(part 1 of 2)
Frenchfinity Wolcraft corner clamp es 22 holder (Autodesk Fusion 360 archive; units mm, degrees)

design "Wolcraft corner clamp es 22 holder" references "Base"
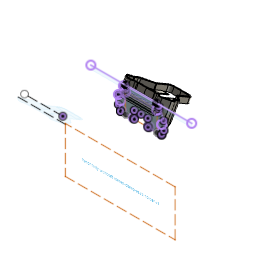
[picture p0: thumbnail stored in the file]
parameter "padding" = 2
parameter "wall_thickness" = 3
component_insert "Component Insert"
canvas "Canvas5"
sketch "Reference" plane through (0, 0, 0) normal (0, 0, 1) x axis (1, 0, 0)
  line L1 (7.1498, 37.8606) -> (8.7854, 10.1726)
  line L2 (26.4622, -5.6256) -> (8.7854, 10.1726)
  line L3 (28.6559, -18.1029) -> (28.1216, -9.0589)
  line L4 (34.1914, -23.0501) -> (28.6559, -18.1029)
  line L5 (25.086, -36.2395) -> (34.3498, -25.8741)
  line L6 (15.5018, -31.9562) -> (22.4922, -36.5753)
  line L7 (11, -31.9562) -> (15.5018, -31.9562)
  line L8 (9.4019, -31.2884) -> (11, -31.9562)
  line L9 (-7.5524, -32.5215) -> (-11.7572, 42.0357)
  line L10 (-7.5524, -32.5215) -> (9.4019, -31.2884)
  line L11 (-11.7572, 42.0357) -> (1.9669, 42.5621)
  line L12 (-7.5524, -32.5215) -> (-24.5378, -33.2026)
  line L13 (-24.5378, -33.2026) -> (-26.0507, -34.0457)
  line L14 (-26.0507, -34.0457) -> (-30.5239, -34.5519)
  line L15 (-30.5239, -34.5519) -> (-36.9506, -39.9278)
  line L16 (-39.5658, -39.8857) -> (-49.9363, -30.6276)
  line L17 (-50.0964, -27.8037) -> (-45.1522, -22.2655)
  line L18 (-45.1522, -22.2655) -> (-45.6382, -13.2187)
  line L19 (-44.3754, -9.6207) -> (-28.587, 8.0649)
  line L20 (-30.075, 35.7612) -> (-28.587, 8.0649)
  line L21 (-11.7572, 42.0357) -> (-25.4535, 41.0157)
  arc A1 centre (2.1585, 37.5658) radius 5 clockwise from (1.9669, 42.5621) to (7.1498, 37.8606)
  arc A2 centre (23.1303, -9.3537) radius 5 clockwise from (26.4622, -5.6256) to (28.1216, -9.0589)
  arc A3 centre (32.8586, -24.5413) radius 2 clockwise from (34.1914, -23.0501) to (34.3498, -25.8741)
  arc A4 centre (23.5948, -34.9067) radius 2 clockwise from (25.086, -36.2395) to (22.4922, -36.5753)
  arc A5 centre (-38.2338, -38.3937) radius 2 clockwise from (-36.9506, -39.9278) to (-39.5658, -39.8857)
  arc A6 centre (-48.6044, -29.1356) radius 2 clockwise from (-49.9363, -30.6276) to (-50.0964, -27.8037)
  arc A7 centre (-40.6455, -12.9505) radius 5 clockwise from (-45.6382, -13.2187) to (-44.3754, -9.6207)
  arc A8 centre (-25.0822, 36.0295) radius 5 clockwise from (-30.075, 35.7612) to (-25.4535, 41.0157)
  point P2 (8.7854, 10.1726)
  point P35 (-28.587, 8.0649)
  point P3 (9.4019, -31.2884)
  point P21 (-24.5378, -33.2026)
  point P4 (28.6559, -18.1029)
  point P31 (-45.1522, -22.2655)
  point P5 (15.5018, -31.9562)
  point P24 (-30.5239, -34.5519)
  point P6 (11, -31.9562)
  point P23 (-26.0507, -34.0457)
  point P7 (-11.7572, 42.0357)
  point P39 (-11.7572, 42.0357)
  point P8 (-7.5524, -32.5215)
  point P22 (-7.5524, -32.5215)
  point P9 (7.1498, 37.8606)
  point P36 (-30.075, 35.7612)
  point P10 (1.9669, 42.5621)
  point P38 (-25.4535, 41.0157)
  point P12 (26.4622, -5.6256)
  point P34 (-44.3754, -9.6207)
  point P13 (28.1216, -9.0589)
  point P32 (-45.6382, -13.2187)
  point P15 (34.1914, -23.0501)
  point P30 (-50.0964, -27.8037)
  point P16 (34.3498, -25.8741)
  point P28 (-49.9363, -30.6276)
  point P18 (25.086, -36.2395)
  point P27 (-39.5658, -39.8857)
  point P19 (22.4922, -36.5753)
  point P25 (-36.9506, -39.9278)
  parallel L2 L4
  perpendicular L4 L5
  horizontal L7
  tangent L1 A1
  tangent L11 A1
  tangent L2 A2
  tangent L3 A2
  equal A1 A2
  tangent L4 A3
  tangent L5 A3
  tangent L5 A4
  tangent L6 A4
  symmetric P2 L9 P35
  symmetric P3 L9 P21
  symmetric P4 L9 P31
  symmetric P5 L9 P24
  symmetric P6 L9 P23
  symmetric P7 L9 P39
  symmetric P8 L9 P22
  symmetric L9 P9 P36
  symmetric L9 P10 P38
  symmetric L9 A1 A8
  symmetric L9 P12 P34
  symmetric L9 P13 P32
  symmetric L9 A2 A7
  symmetric L9 P15 P30
  symmetric L9 P16 P28
  symmetric L9 A3 A6
  symmetric L9 P18 P27
  symmetric L9 P19 P25
  symmetric L9 A4 A5
  dimension "d60" radius A1 = 5
  dimension "d61" radius A3 = 2
  dimension "d62" radius A4 = 2
sketch "Correct size" plane through (0, 0, 0) normal (0, 0, 1) x axis (1, 0, 0)
  line L1 (-7.5524, -32.5215) -> (-24.5378, -33.2026)
  line L2 (-24.5378, -33.2026) -> (-26.0507, -34.0457)
  line L3 (-26.0507, -34.0457) -> (-30.5239, -34.5519)
  line L4 (-30.5239, -34.5519) -> (-36.9506, -39.9278)
  line L5 (-39.5658, -39.8857) -> (-49.9363, -30.6276)
  line L6 (-50.0964, -27.8037) -> (-45.1522, -22.2655)
  line L7 (-45.1522, -22.2655) -> (-45.6382, -13.2187)
  line L8 (-44.3754, -9.6207) -> (-28.587, 8.0649)
  line L9 (-11.7572, 42.0357) -> (-25.4535, 41.0157)
  line L10 (-30.075, 35.7612) -> (-28.587, 8.0649)
  line L11 (-11.7572, 42.0357) -> (1.9669, 42.5621)
  line L12 (-7.5524, -32.5215) -> (9.4019, -31.2884)
  line L13 (9.4019, -31.2884) -> (11, -31.9562)
  line L14 (11, -31.9562) -> (15.5018, -31.9562)
  line L15 (15.5018, -31.9562) -> (22.4922, -36.5753)
  line L16 (25.086, -36.2395) -> (34.3498, -25.8741)
  line L17 (34.1914, -23.0501) -> (28.6559, -18.1029)
  line L18 (28.6559, -18.1029) -> (28.1216, -9.0589)
  line L19 (26.4622, -5.6256) -> (8.7854, 10.1726)
  line L20 (7.1498, 37.8606) -> (8.7854, 10.1726)
  line L21 (-11.7009, 41.0371) -> (2.0052, 41.5629)
  line L22 (-11.7009, 41.0371) -> (-25.3792, 40.0184)
  line L23 (-29.0764, 35.8149) -> (-27.5663, 7.7066)
  line L24 (-43.6294, -10.2867) -> (-27.5663, 7.7066)
  line L25 (-44.1315, -22.6237) -> (-44.6397, -13.1651)
  line L26 (-49.3504, -28.4697) -> (-44.1315, -22.6237)
  line L27 (-38.8998, -39.1397) -> (-49.2703, -29.8816)
  line L28 (-30.935, -33.592) -> (-37.5922, -39.1607)
  line L29 (-26.3624, -33.0746) -> (-30.935, -33.592)
  line L30 (-24.8163, -32.2129) -> (-26.3624, -33.0746)
  line L31 (-7.6087, -31.5229) -> (-24.8163, -32.2129)
  line L32 (-7.6087, -31.5229) -> (9.5674, -30.2738)
  line L33 (9.5674, -30.2738) -> (11.2005, -30.9562)
  line L34 (11.2005, -30.9562) -> (15.8023, -30.9562)
  line L35 (15.8023, -30.9562) -> (23.0435, -35.741)
  line L36 (24.3404, -35.5731) -> (33.6042, -25.2077)
  line L37 (33.525, -23.7957) -> (27.6819, -18.5736)
  line L38 (27.6819, -18.5736) -> (27.1234, -9.1178)
  line L39 (25.7958, -6.3712) -> (7.8115, 9.7019)
  line L40 (6.1516, 37.8017) -> (7.8115, 9.7019)
  line L41 (-11.7009, 41.0371) -> (-7.6087, -31.5229)
  line L42 (7.8115, 9.7019) -> (-27.5663, 7.7066)
  arc A1 centre (-38.2338, -38.3937) radius 2 clockwise from (-36.9506, -39.9278) to (-39.5658, -39.8857)
  arc A2 centre (-48.6044, -29.1356) radius 2 clockwise from (-49.9363, -30.6276) to (-50.0964, -27.8037)
  arc A3 centre (-40.6455, -12.9505) radius 5 clockwise from (-45.6382, -13.2187) to (-44.3754, -9.6207)
  arc A4 centre (-25.0822, 36.0295) radius 5 clockwise from (-30.075, 35.7612) to (-25.4535, 41.0157)
  arc A5 centre (23.5948, -34.9067) radius 2 clockwise from (25.086, -36.2395) to (22.4922, -36.5753)
  arc A6 centre (32.8586, -24.5413) radius 2 clockwise from (34.1914, -23.0501) to (34.3498, -25.8741)
  arc A7 centre (23.1303, -9.3537) radius 5 clockwise from (26.4622, -5.6256) to (28.1216, -9.0589)
  arc A8 centre (2.1585, 37.5658) radius 5 clockwise from (1.9669, 42.5621) to (7.1498, 37.8606)
  arc A9 centre (-25.0822, 36.0295) radius 4 clockwise from (-29.0764, 35.8149) to (-25.3792, 40.0184)
  arc A10 centre (-40.6455, -12.9505) radius 4 clockwise from (-44.6397, -13.1651) to (-43.6294, -10.2867)
  arc A11 centre (-48.6044, -29.1356) radius 1 clockwise from (-49.2703, -29.8816) to (-49.3504, -28.4697)
  arc A12 centre (-38.2338, -38.3937) radius 1 clockwise from (-37.5922, -39.1607) to (-38.8998, -39.1397)
  arc A13 centre (23.5948, -34.9067) radius 1 clockwise from (24.3404, -35.5731) to (23.0435, -35.741)
  arc A14 centre (32.8586, -24.5413) radius 1 clockwise from (33.525, -23.7957) to (33.6042, -25.2077)
  arc A15 centre (23.1303, -9.3537) radius 4 clockwise from (25.7958, -6.3712) to (27.1234, -9.1178)
  arc A16 centre (2.1585, 37.5658) radius 4 clockwise from (2.0052, 41.5629) to (6.1516, 37.8017)
  point P41 (-11.7009, 41.0371)
  point P59 (-7.6087, -31.5229)
  point P45 (-27.5663, 7.7066)
  point P73 (7.8115, 9.7019)
  dimension "d64" = -1
  dimension "d65" distance P41 P59 = 72.56
  dimension "d66" distance P45 P73 = 35.3778
sketch "Base" plane through (0, 0, 0) normal (0, 0, 1) x axis (1, 0, 0)
  line L1 (-11.7009, 41.0371) -> (-25.3792, 40.0184)
  line L2 (-11.7009, 41.0371) -> (2.0052, 41.5629)
  line L3 (6.1516, 37.8017) -> (7.8115, 9.7019)
  line L4 (25.7958, -6.3712) -> (7.8115, 9.7019)
  line L5 (27.6819, -18.5736) -> (27.1234, -9.1178)
  line L6 (33.525, -23.7957) -> (27.6819, -18.5736)
  line L7 (24.3404, -35.5731) -> (33.6042, -25.2077)
  line L8 (15.8023, -30.9562) -> (23.0435, -35.741)
  line L9 (11.2005, -30.9562) -> (15.8023, -30.9562)
  line L10 (9.5674, -30.2738) -> (11.2005, -30.9562)
  line L11 (-7.6087, -31.5229) -> (9.5674, -30.2738)
  line L12 (-7.6087, -31.5229) -> (-24.8163, -32.2129)
  line L13 (-24.8163, -32.2129) -> (-26.3624, -33.0746)
  line L14 (-26.3624, -33.0746) -> (-30.935, -33.592)
  line L15 (-30.935, -33.592) -> (-37.5922, -39.1607)
  line L16 (-38.8998, -39.1397) -> (-49.2703, -29.8816)
  line L17 (-49.3504, -28.4697) -> (-44.1315, -22.6237)
  line L18 (-44.1315, -22.6237) -> (-44.6397, -13.1651)
  line L19 (-43.6294, -10.2867) -> (-27.5663, 7.7066)
  line L20 (-29.0764, 35.8149) -> (-27.5663, 7.7066)
  line L21 (-11.8135, 43.0342) -> (1.9286, 43.5614)
  line L22 (-11.8135, 43.0342) -> (-25.5278, 42.0129)
  line L23 (-31.0735, 35.7076) -> (-29.6077, 8.4231)
  line L24 (-45.1214, -8.9547) -> (-29.6077, 8.4231)
  line L25 (-46.1729, -21.9072) -> (-46.6368, -13.2724)
  line L26 (-50.8423, -27.1378) -> (-46.1729, -21.9072)
  line L27 (-40.2317, -40.6316) -> (-50.6023, -31.3736)
  line L28 (-30.1128, -35.5118) -> (-36.309, -40.6948)
  line L29 (-25.739, -35.0169) -> (-30.1128, -35.5118)
  line L30 (-24.2594, -34.1922) -> (-25.739, -35.0169)
  line L31 (-7.4961, -33.52) -> (-24.2594, -34.1922)
  line L32 (-7.4961, -33.52) -> (9.2365, -32.3031)
  line L33 (9.2365, -32.3031) -> (10.7995, -32.9562)
  line L34 (10.7995, -32.9562) -> (15.2012, -32.9562)
  line L35 (15.2012, -32.9562) -> (21.9409, -37.4096)
  line L36 (25.8316, -36.9058) -> (35.0955, -26.5404)
  line L37 (34.8577, -22.3045) -> (29.6298, -17.6321)
  line L38 (29.6298, -17.6321) -> (29.1199, -8.9999)
  line L39 (27.1286, -4.88) -> (9.7594, 10.6433)
  line L40 (8.1481, 37.9196) -> (9.7594, 10.6433)
  line L41 (-11.9825, 46.03) -> (1.8136, 46.5592)
  line L42 (-11.9825, 46.03) -> (-25.7506, 45.0046)
  line L43 (-34.0692, 35.5467) -> (-32.6698, 9.4979)
  line L44 (-47.3593, -6.9569) -> (-32.6698, 9.4979)
  line L45 (-49.235, -20.8325) -> (-49.6325, -13.4333)
  line L46 (-53.0803, -25.1399) -> (-49.235, -20.8325)
  line L47 (-42.2296, -42.8696) -> (-52.6002, -33.6116)
  line L48 (-28.8796, -38.3914) -> (-34.3842, -42.9959)
  line L49 (-24.8039, -37.9302) -> (-28.8796, -38.3914)
  line L50 (-23.424, -37.1611) -> (-24.8039, -37.9302)
  line L51 (-7.3271, -36.5157) -> (-23.424, -37.1611)
  line L52 (-7.3271, -36.5157) -> (8.7403, -35.3471)
  line L53 (8.7403, -35.3471) -> (10.1979, -35.9562)
  line L54 (10.1979, -35.9562) -> (14.2996, -35.9562)
  line L55 (14.2996, -35.9562) -> (20.287, -39.9126)
  line L56 (28.0685, -38.905) -> (37.3323, -28.5396)
  line L57 (36.8569, -20.0676) -> (32.5516, -16.2199)
  line L58 (32.5516, -16.2199) -> (32.1147, -8.823)
  line L59 (29.1277, -2.6432) -> (12.6812, 12.0556)
  line L60 (11.1429, 38.0965) -> (12.6812, 12.0556)
  line L61 (-7.4961, -33.52) -> (-7.6087, -31.5229)
  line L62 (-7.9465, -25.5327) -> (-7.4961, -33.52)
  line L63 (-21.4357, -26.0736) -> (-7.9465, -25.5327)
  line L64 (-21.9988, -16.0895) -> (-21.4357, -26.0736)
  line L65 (-11.7009, 41.0371) -> (-7.6087, -31.5229)
  line L66 (-8.5096, -15.5486) -> (-21.9988, -16.0895)
  line L67 (-15.504, -15.829) -> (-8.5096, -15.5486)
  line L68 (-18.7944, 42.5144) -> (-15.504, -15.829)
  line L69 (-7.5524, -32.5215) -> (-11.7572, 42.0357)
  line L70 (-11.8135, 43.0342) -> (-11.7009, 41.0371)
  line L71 (-11.0252, 29.0564) -> (-11.8135, 43.0342)
  line L72 (-30.6595, 28.0016) -> (-11.0252, 29.0564)
  line L73 (8.6032, 30.2159) -> (-11.0252, 29.0564)
  line L74 (-4.8185, 43.3026) -> (-1.5281, -15.0408)
  line L75 (-8.5096, -15.5486) -> (4.9548, -14.5693)
  line L76 (4.9548, -14.5693) -> (5.5179, -24.5535)
  line L77 (5.5179, -24.5535) -> (-7.9465, -25.5327)
  arc A1 centre (-25.0822, 36.0295) radius 4 clockwise from (-29.0764, 35.8149) to (-25.3792, 40.0184)
  arc A2 centre (2.1585, 37.5658) radius 4 clockwise from (2.0052, 41.5629) to (6.1516, 37.8017)
  arc A3 centre (23.1303, -9.3537) radius 4 clockwise from (25.7958, -6.3712) to (27.1234, -9.1178)
  arc A4 centre (32.8586, -24.5413) radius 1 clockwise from (33.525, -23.7957) to (33.6042, -25.2077)
  arc A5 centre (23.5948, -34.9067) radius 1 clockwise from (24.3404, -35.5731) to (23.0435, -35.741)
  arc A6 centre (-38.2338, -38.3937) radius 1 clockwise from (-37.5922, -39.1607) to (-38.8998, -39.1397)
  arc A7 centre (-48.6044, -29.1356) radius 1 clockwise from (-49.2703, -29.8816) to (-49.3504, -28.4697)
  arc A8 centre (-40.6455, -12.9505) radius 4 clockwise from (-44.6397, -13.1651) to (-43.6294, -10.2867)
  arc A9 centre (-25.0822, 36.0295) radius 6 clockwise from (-31.0735, 35.7076) to (-25.5278, 42.0129)
  arc A10 centre (-40.6455, -12.9505) radius 6 clockwise from (-46.6368, -13.2724) to (-45.1214, -8.9547)
  arc A11 centre (-48.6044, -29.1356) radius 3 clockwise from (-50.6023, -31.3736) to (-50.8423, -27.1378)
  arc A12 centre (-38.2338, -38.3937) radius 3 clockwise from (-36.309, -40.6948) to (-40.2317, -40.6316)
  arc A13 centre (23.5948, -34.9067) radius 3 clockwise from (25.8316, -36.9058) to (21.9409, -37.4096)
  arc A14 centre (32.8586, -24.5413) radius 3 clockwise from (34.8577, -22.3045) to (35.0955, -26.5404)
  arc A15 centre (23.1303, -9.3537) radius 6 clockwise from (27.1286, -4.88) to (29.1199, -8.9999)
  arc A16 centre (2.1585, 37.5658) radius 6 clockwise from (1.9286, 43.5614) to (8.1481, 37.9196)
  arc A17 centre (-25.0822, 36.0295) radius 9 clockwise from (-34.0692, 35.5467) to (-25.7506, 45.0046)
  arc A18 centre (-40.6455, -12.9505) radius 9 clockwise from (-49.6325, -13.4333) to (-47.3593, -6.9569)
  arc A19 centre (-48.6044, -29.1356) radius 6 clockwise from (-52.6002, -33.6116) to (-53.0803, -25.1399)
  arc A20 centre (-38.2338, -38.3937) radius 6 clockwise from (-34.3842, -42.9959) to (-42.2296, -42.8696)
  arc A21 centre (23.5948, -34.9067) radius 6 clockwise from (28.0685, -38.905) to (20.287, -39.9126)
  arc A22 centre (32.8586, -24.5413) radius 6 clockwise from (36.8569, -20.0676) to (37.3323, -28.5396)
  arc A23 centre (23.1303, -9.3537) radius 9 clockwise from (29.1277, -2.6432) to (32.1147, -8.823)
  arc A24 centre (2.1585, 37.5658) radius 9 clockwise from (1.8136, 46.5592) to (11.1429, 38.0965)
  point P23 (-7.6087, -31.5229)
  point P110 (-7.6087, -31.5229)
  point P116 (-18.7944, 42.5144)
  point P5 (-11.7009, 41.0371)
  point P119 (-11.7009, 41.0371)
  point P121 (-30.6595, 28.0016)
  point P111 (-7.9465, -25.5327)
  point P129 (-7.9465, -25.5327)
  point P112 (-21.4357, -26.0736)
  point P128 (5.5179, -24.5535)
  point P113 (-21.9988, -16.0895)
  point P126 (4.9548, -14.5693)
  point P114 (-8.5096, -15.5486)
  point P127 (-8.5096, -15.5486)
  point P115 (-15.504, -15.829)
  point P124 (-1.5281, -15.0408)
  point P125 (-4.8185, 43.3026)
  point P120 (-11.0252, 29.0564)
  point P122 (-11.0252, 29.0564)
  point P123 (8.6032, 30.2159)
  point P57 (-7.4961, -33.52)
  point P39 (-11.8135, 43.0342)
  coincident P23 P110
  parallel L61 L62
  parallel L12 L63
  parallel L64 L65
  parallel L63 L66
  parallel L66 L67
  coincident L22 P116
  parallel L68 L69
  coincident P5 P119
  parallel L65 L71
  coincident L23 P121
  perpendicular L23 L72
  symmetric P111 L65 P129
  symmetric P112 L65 P128
  symmetric P113 L65 P126
  symmetric L65 P114 P127
  symmetric L65 P115 P124
  symmetric L65 P116 P125
  symmetric L65 P120 P122
  symmetric L65 P121 P123
  dimension "d67" = -2 (= "padding * -1")
  dimension "d68" = -5 (= "( padding + wall_thickness ) * -1")
  dimension "d74" distance P57 P111 = 8
  dimension "d75" distance P111 P112 = 13.5
  dimension "d76" distance P112 P113 = 10
  dimension "d77" distance P113 P114 = 13.5
  dimension "d78" distance P114 P115 = 7
  dimension "d79" distance P39 P120 = 14
extrude "Extrude8" new body sketch "Base" profile of A16 L40 L39 A15 L34 A14 L33 L31 L32 L30 L29 L28 L24 L35 L26 A9 L27 A10 L36 A12 L37 L23 L21 A11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 along normal blind 10
sketch "Sketch16" plane through (0, 0, 0) normal (0, 0, 1) x axis (1, 0, 0)
  line L1 (-11.9825, 46.03) -> (-25.7506, 45.0046)
  line L2 (-11.9825, 46.03) -> (1.8136, 46.5592)
  line L3 (11.1429, 38.0965) -> (12.6812, 12.0556)
  line L4 (29.1277, -2.6432) -> (12.6812, 12.0556)
  line L5 (32.5516, -16.2199) -> (32.1147, -8.823)
  line L6 (36.8569, -20.0676) -> (32.5516, -16.2199)
  line L7 (28.0685, -38.905) -> (37.3323, -28.5396)
  line L8 (14.2996, -35.9562) -> (20.287, -39.9126)
  line L9 (10.1979, -35.9562) -> (14.2996, -35.9562)
  line L10 (8.7403, -35.3471) -> (10.1979, -35.9562)
  line L11 (-7.3271, -36.5157) -> (8.7403, -35.3471)
  line L12 (-7.3271, -36.5157) -> (-23.424, -37.1611)
  line L13 (-23.424, -37.1611) -> (-24.8039, -37.9302)
  line L14 (-24.8039, -37.9302) -> (-28.8796, -38.3914)
  line L15 (-28.8796, -38.3914) -> (-34.3842, -42.9959)
  line L16 (-42.2296, -42.8696) -> (-52.6002, -33.6116)
  line L17 (-53.0803, -25.1399) -> (-49.235, -20.8325)
  line L18 (-49.235, -20.8325) -> (-49.6325, -13.4333)
  line L19 (-47.3593, -6.9569) -> (-32.6698, 9.4979)
  line L20 (-34.0692, 35.5467) -> (-32.6698, 9.4979)
  line L21 (-7.4961, -33.52) -> (-24.2594, -34.1922)
  line L22 (-24.2594, -34.1922) -> (-25.739, -35.0169)
  line L23 (-25.739, -35.0169) -> (-30.1128, -35.5118)
  line L24 (-30.1128, -35.5118) -> (-36.309, -40.6948)
  line L25 (-40.2317, -40.6316) -> (-50.6023, -31.3736)
  line L26 (-50.8423, -27.1378) -> (-46.1729, -21.9072)
  line L27 (-46.1729, -21.9072) -> (-46.6368, -13.2724)
  line L28 (-45.1214, -8.9547) -> (-29.6077, 8.4231)
  line L29 (-11.8135, 43.0342) -> (-25.5278, 42.0129)
  line L30 (-11.8135, 43.0342) -> (1.9286, 43.5614)
  line L31 (8.1481, 37.9196) -> (9.7594, 10.6433)
  line L32 (27.1286, -4.88) -> (9.7594, 10.6433)
  line L33 (29.6298, -17.6321) -> (29.1199, -8.9999)
  line L34 (34.8577, -22.3045) -> (29.6298, -17.6321)
  line L35 (25.8316, -36.9058) -> (35.0955, -26.5404)
  line L36 (15.2012, -32.9562) -> (21.9409, -37.4096)
  line L37 (10.7995, -32.9562) -> (15.2012, -32.9562)
  line L38 (9.2365, -32.3031) -> (10.7995, -32.9562)
  line L39 (-7.4961, -33.52) -> (9.2365, -32.3031)
  line L40 (-31.0735, 35.7076) -> (-29.6077, 8.4231)
  line L41 (-18.7944, 42.5144) -> (-15.504, -15.829)
  line L42 (-4.8185, 43.3026) -> (-1.5281, -15.0408)
  line L43 (-8.5096, -15.5486) -> (-21.9988, -16.0895)
  line L44 (-21.9988, -16.0895) -> (-21.4357, -26.0736)
  line L45 (-21.4357, -26.0736) -> (-7.9465, -25.5327)
  line L46 (5.5179, -24.5535) -> (-7.9465, -25.5327)
  line L47 (4.9548, -14.5693) -> (5.5179, -24.5535)
  line L48 (-8.5096, -15.5486) -> (4.9548, -14.5693)
  line L49 (8.6032, 30.2159) -> (-11.0252, 29.0564)
  line L50 (-30.6595, 28.0016) -> (-11.0252, 29.0564)
  arc A1 centre (-25.0822, 36.0295) radius 9 clockwise from (-34.0692, 35.5467) to (-25.7506, 45.0046)
  arc A2 centre (2.1585, 37.5658) radius 9 clockwise from (1.8136, 46.5592) to (11.1429, 38.0965)
  arc A3 centre (23.1303, -9.3537) radius 9 clockwise from (29.1277, -2.6432) to (32.1147, -8.823)
  arc A4 centre (32.8586, -24.5413) radius 6 clockwise from (36.8569, -20.0676) to (37.3323, -28.5396)
  arc A5 centre (23.5948, -34.9067) radius 6 clockwise from (28.0685, -38.905) to (20.287, -39.9126)
  arc A6 centre (-38.2338, -38.3937) radius 6 clockwise from (-34.3842, -42.9959) to (-42.2296, -42.8696)
  arc A7 centre (-48.6044, -29.1356) radius 6 clockwise from (-52.6002, -33.6116) to (-53.0803, -25.1399)
  arc A8 centre (-40.6455, -12.9505) radius 9 clockwise from (-49.6325, -13.4333) to (-47.3593, -6.9569)
  arc A9 centre (-38.2338, -38.3937) radius 3 clockwise from (-36.309, -40.6948) to (-40.2317, -40.6316)
  arc A10 centre (-48.6044, -29.1356) radius 3 clockwise from (-50.6023, -31.3736) to (-50.8423, -27.1378)
  arc A11 centre (-40.6455, -12.9505) radius 6 clockwise from (-46.6368, -13.2724) to (-45.1214, -8.9547)
  arc A12 centre (-25.0822, 36.0295) radius 6 clockwise from (-31.0735, 35.7076) to (-25.5278, 42.0129)
  arc A13 centre (2.1585, 37.5658) radius 6 clockwise from (1.9286, 43.5614) to (8.1481, 37.9196)
  arc A14 centre (23.1303, -9.3537) radius 6 clockwise from (27.1286, -4.88) to (29.1199, -8.9999)
  arc A15 centre (32.8586, -24.5413) radius 3 clockwise from (34.8577, -22.3045) to (35.0955, -26.5404)
  arc A16 centre (23.5948, -34.9067) radius 3 clockwise from (25.8316, -36.9058) to (21.9409, -37.4096)
extrude "Extrude9" add sketch "Sketch16" against normal blind 1
move "Move1"
sketch "Sketch17" plane through (0, 0, 0) normal (0, 0, 1) x axis (1, 0, 0)
  line L1 (-76, 0) -> (0, 0)
  point P1 (0, 0)
  point P2 (0, 0)
  coincident P1 P2
  horizontal L1
move "Move2"
move "Move3"
move "Move4"
move "Move5"
move "Move6"
sketch "Sketch18" plane through (0, 0, 0) normal (1, 0, 0) x axis (0, 1, 0)
  line L1 (-2.1019, -8.6882) -> (-2.2977, -8.5751)
  line L2 (6.5584, -13.6882) -> (-2.1019, -8.6882)
  line L3 (6.4641, -13.6337) -> (6.5584, -13.6882)
  line L4 (45.0721, -35.9241) -> (6.4641, -13.6337)
  line L5 (45.1067, -35.9441) -> (45.0721, -35.9241)
  line L6 (51.7899, -39.8026) -> (45.1067, -35.9441)
  line L7 (51.7899, -39.8026) -> (56.9689, -42.7927)
  line L8 (57.1774, -42.9131) -> (56.9689, -42.7927)
  line L9 (56.9572, -42.786) -> (57.1774, -42.9131)
  line L10 (51.7733, -39.793) -> (56.9572, -42.786)
  line L11 (45.0901, -35.9345) -> (51.7733, -39.793)
  line L12 (45.0662, -35.9207) -> (45.0901, -35.9345)
  line L13 (6.4582, -13.6303) -> (45.0662, -35.9207)
  line L14 (6.547, -13.6816) -> (6.4582, -13.6303)
  line L15 (-2.1133, -8.6816) -> (6.547, -13.6816)
  line L16 (-2.2977, -8.5751) -> (-2.1133, -8.6816)
  line L17 (15.6697, -18.9486) -> (10.1796, -15.7789)
  line L18 (29.1876, -26.7531) -> (15.6697, -18.9486)
  line L19 (51.779, -39.7963) -> (29.1876, -26.7531)
  line L20 (59.5549, -44.2857) -> (51.779, -39.7963)
  line L21 (59.7759, -44.4133) -> (59.5549, -44.2857)
  line L22 (59.5665, -44.2924) -> (59.7759, -44.4133)
  line L23 (59.5665, -44.2924) -> (51.7981, -39.8073)
  line L24 (29.2067, -26.7642) -> (51.7981, -39.8073)
  line L25 (15.702, -18.9673) -> (29.2067, -26.7642)
  line L26 (15.702, -18.9673) -> (10.2141, -15.7988)
  line L27 (3.7971, -12.0939) -> (10.2141, -15.7988)
  line L28 (0.2619, -10.0529) -> (3.7971, -12.0939)
  line L29 (0.2619, -10.0529) -> (-7.0866, -5.8103)
  line L30 (-15.6014, -0.8942) -> (-7.0866, -5.8103)
  line L31 (-15.6014, -0.8942) -> (-17.1241, -0.0151)
  line L32 (-12.386, -2.7506) -> (-16.0965, -0.6084)
  line L33 (-12.1878, -2.8651) -> (-12.386, -2.7506)
  line L34 (-11.5907, -3.2098) -> (-12.1878, -2.8651)
  line L35 (-11.8243, -3.0749) -> (-11.5907, -3.2098)
  line L36 (-11.6043, -3.202) -> (-11.8243, -3.0749)
  line L37 (-12.2026, -2.8565) -> (-11.6043, -3.202)
  line L38 (-12.4043, -2.7401) -> (-12.2026, -2.8565)
  line L39 (-16.1196, -0.595) -> (-12.4043, -2.7401)
  line L40 (-15.6311, -0.8771) -> (-17.1502, 0)
  line L41 (-7.1246, -5.7883) -> (-15.6311, -0.8771)
  line L42 (0.2239, -10.031) -> (-7.1246, -5.7883)
  line L43 (3.7625, -12.074) -> (0.2239, -10.031)
  line L44 (10.1796, -15.7789) -> (3.7625, -12.074)
  line L45 (-17.1241, -50.0151) -> (-17.1241, -0.0151)
  line L46 (29.2067, -26.7642) -> (34.7067, -17.2379)
  line L47 (-17.1241, -50.0151) -> (29.2067, -26.7642)
  point P33 (-17.1241, -0.0151)
  point P48 (-17.1241, -0.0151)
  point P51 (29.2067, -26.7642)
  point P52 (29.2067, -26.7642)
  point P49 (-17.1241, -50.0151)
  vertical L45
  coincident P33 P48
  coincident P51 P52
  dimension "d82" distance P48 P49 = 50
sketch "Sketch19" plane through (0, -4.2876, -7.4263) normal (0, -0.5, -0.866) x axis (1, 0, 0)
  line L1 (-24.5019, -2.5238) -> (-38, -2.2977)
  line L2 (-24.5068, -12.5238) -> (-24.5019, -2.5238)
  line L3 (-31.0059, -12.4149) -> (-24.5068, -12.5238)
  line L4 (-31.0276, -56.9957) -> (-31.0059, -12.4149)
  line L5 (-18.3641, -57.0356) -> (-31.0276, -56.9957)
  line L6 (-18.3885, -64.7527) -> (-18.3641, -57.0356)
  line L7 (-38.0335, -70.9736) -> (-24.2834, -70.7328)
  line L8 (-51.7833, -70.7194) -> (-38.0335, -70.9736)
  line L9 (-57.6892, -57.0164) -> (-57.6724, -64.7335)
  line L10 (-45.0257, -56.9888) -> (-57.6892, -57.0164)
  line L11 (-45.004, -12.4081) -> (-45.0257, -56.9888)
  line L12 (-51.5032, -12.5106) -> (-45.004, -12.4081)
  line L13 (-51.4983, -2.5106) -> (-51.5032, -12.5106)
  line L14 (-38, -2.2977) -> (-51.4983, -2.5106)
  line L15 (-60.7292, -38.6538) -> (-76.3144, -23.0447)
  line L16 (-60.6724, -64.74) -> (-60.7292, -38.6538)
  line L17 (-38.0349, -73.9741) -> (-51.8388, -73.7189)
  line L18 (-24.2309, -73.7324) -> (-38.0349, -73.9741)
  line L19 (-15.3062, -38.6759) -> (-15.3885, -64.7621)
  line L20 (0.2942, -23.082) -> (-15.3062, -38.6759)
  line L21 (2.9548, -9.3353) -> (2.9315, -16.7451)
  line L22 (7.0386, -5.2533) -> (2.9548, -9.3353)
  line L23 (-2.7876, 13.0641) -> (7.0404, 3.232)
  line L24 (-16.3704, 9.3513) -> (-10.6132, 13.6358)
  line L25 (-20.4657, 9.1224) -> (-16.3704, 9.3513)
  line L26 (-21.887, 8.4329) -> (-20.4657, 9.1224)
  line L27 (-37.9946, 8.7027) -> (-21.887, 8.4329)
  line L28 (-54.1025, 8.4486) -> (-37.9946, 8.7027)
  line L29 (-55.5232, 9.1394) -> (-54.1025, 8.4486)
  line L30 (-59.6182, 9.3724) -> (-55.5232, 9.1394)
  line L31 (-65.3713, 13.6624) -> (-59.6182, 9.3724)
  line L32 (-83.035, 3.2759) -> (-73.1974, 13.0984)
  line L33 (-78.9617, -9.2954) -> (-83.0415, -5.2094)
  line L34 (-78.9456, -16.7052) -> (-78.9617, -9.2954)
  line L35 (8.7969, -1.011) -> (-84.7956, -0.9654)
  arc A1 centre (-24.3884, -64.7337) radius 6 clockwise from (-18.3885, -64.7527) to (-24.2834, -70.7328)
  arc A2 centre (-51.6724, -64.7204) radius 6 clockwise from (-51.7833, -70.7194) to (-57.6724, -64.7335)
  arc A3 centre (-69.9456, -16.6856) radius 9 clockwise from (-76.3144, -23.0447) to (-78.9456, -16.7052)
  arc A4 centre (-51.6724, -64.7204) radius 9 clockwise from (-51.8388, -73.7189) to (-60.6724, -64.74)
  arc A5 centre (-24.3884, -64.7337) radius 9 clockwise from (-15.3885, -64.7621) to (-24.2309, -73.7324)
  arc A6 centre (-6.0685, -16.7167) radius 9 clockwise from (2.9315, -16.7451) to (0.2942, -23.082)
  arc A7 centre (2.7969, -1.0097) radius 6 clockwise from (7.0404, 3.232) to (7.0386, -5.2533)
  arc A8 centre (-7.0311, 8.8224) radius 6 clockwise from (-10.6132, 13.6358) to (-2.7876, 13.0641)
  arc A9 centre (-68.958, 8.8525) radius 6 clockwise from (-73.1974, 13.0984) to (-65.3713, 13.6624)
  arc A10 centre (-78.7956, -0.97) radius 6 clockwise from (-83.0415, -5.2094) to (-83.035, 3.2759)
  point P54 (-84.7956, -0.9654)
  point P55 (8.7969, -1.011)
  midpoint A10 P54
  midpoint A7 P55
extrude "Extrude10" add sketch "Sketch18" profile of L1 L2 L3 L4 L13 L14 L15 L16 L17 L18 L19 L25 L26 L27 L28 L29 L30 L31 L32 L33 L34 L35 L36 L37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 to an object
extrude "Extrude11" add of existing geometry to an object
extrude "Extrude13" cut of existing geometry blind -65
extrude "Extrude14" cut of existing geometry blind -62
extrude "Extrude15" cut sketch "Sketch19" profile of L1 L2 L3 L4 L5 L6 A1 L7 L8 A2 L9 L10 L11 L12 L13 L14 along normal blind 62
extrude "Extrude16" new body of existing geometry blind 50
sketch "Sketch20" plane through (0, 55.6118, 0) normal (0, 1, 0) x axis (-1, 0, 0)
  line L1 (0, 52.6059) -> (-200, 52.6059)
  line L2 (0, 60) -> (0, 52.6059)
  line L3 (-200, 60) -> (0, 60)
  line L4 (-200, 52.6059) -> (-200, 60)
  line L5 (-200, 60) -> (0, 60)
move "Move7"
sketch "Sketch21" plane through (0, 55.6118, 0) normal (0, -1, 0) x axis (1, 0, 0)
  line L1 (113.1884, 10) -> (113.1921, 25.3077)
  line L2 (140.6462, 10) -> (113.1884, 10)
  line L3 (140.6489, 11.6846) -> (140.6462, 10)
  line L4 (144.7326, 19.8488) -> (140.6489, 11.6846)
  line L5 (134.9064, 56.4835) -> (144.7344, 36.8193)
  line L6 (69.3371, 60) -> (130.6629, 60)
  line L7 (68.1349, 60) -> (69.3371, 60)
  line L8 (54.659, 36.9071) -> (64.4966, 56.5522)
  line L9 (58.7323, 11.7645) -> (54.6525, 19.9366)
  line L10 (58.7342, 10) -> (58.7323, 11.7645)
  line L11 (86.192, 10) -> (58.7342, 10)
  line L12 (86.1957, 25.334) -> (86.192, 10)
  line L13 (99.694, 25.7599) -> (86.1957, 25.334)
  line L14 (113.1921, 25.3077) -> (99.694, 25.7599)
  line L15 (54.659, 36.9071) -> (64.4966, 56.5522)
  closed curve K1 centre (140.4909, 28.3358)
  closed curve K2 centre (130.6629, 48)
  closed curve K3 centre (68.736, 48.0604)
  closed curve K4 centre (58.8984, 28.4154)
extrude "Extrude17" add of existing geometry to an object
extrude "Extrude18" cut of existing geometry to an object
fillet "Fillet5" radius 1 2
sketch "Text" plane through (0, 55.6118, 0) normal (0, -1, 0) x axis (1, 0, 0)
  line L1 (86.1957, 25.334) -> (86.1925, 12.2368)
  line L2 (99.694, 25.7599) -> (86.1957, 25.334)
  line L3 (113.1921, 25.3077) -> (99.694, 25.7599)
  line L4 (113.1889, 12.2386) -> (113.1921, 25.3077)
  line L5 (139.8062, 10) -> (115.1892, 10)
  line L6 (140.2637, 10.9145) -> (139.8062, 10)
  line L7 (144.7326, 19.8488) -> (140.5009, 11.3888)
  line L8 (134.9064, 56.4835) -> (144.7344, 36.8193)
  line L9 (69.3371, 60) -> (130.6629, 60)
  line L10 (68.1349, 60) -> (69.3371, 60)
  line L11 (54.659, 36.9071) -> (64.4966, 56.5522)
  line L12 (58.8144, 11.6002) -> (54.6525, 19.9366)
  line L13 (59.6132, 10) -> (59.2418, 10.7441)
  line L14 (84.1928, 10) -> (59.6132, 10)
  line L15 (68.736, 52.4859) -> (68.736, 47.1259)
  line L16 (134.9064, 52.4859) -> (68.736, 52.4859)
  line L17 (134.9064, 47.1259) -> (134.9064, 52.4859)
  line L18 (68.736, 47.1259) -> (134.9064, 47.1259)
  line L19 (69.3371, 10) -> (68.1349, 60)
  line L20 (131.8651, 10) -> (130.6629, 60)
  curve K1
  curve K2
  curve K3
  curve K4
  closed curve K5 centre (84.1925, 12.2377)
  closed curve K6 centre (115.1889, 12.2377)
  closed curve K7 centre (138.6497, 12.2377)
  closed curve K8 centre (140.4909, 28.3358)
  closed curve K9 centre (130.6629, 48)
  closed curve K10 centre (68.736, 48.0604)
  closed curve K11 centre (58.8984, 28.4154)
  closed curve K12 centre (60.7318, 12.2377)
  point P22 (68.1349, 60)
  point P36 (68.1349, 60)
  point P37 (69.3371, 10)
  point P19 (130.6629, 60)
  point P38 (130.6629, 60)
  point P39 (131.8651, 10)
  coincident P22 P36
  coincident L14 P37
  coincident P19 P38
  coincident L5 P39
  parallel L19 L20
  coincident P39
  coincident P22
  dimension "d105" Text1-Height = 3
extrude "Extrude19" cut sketch "Text" against normal blind 2
sketch "Filename" plane through (0, 0, 0) normal (0, 1, 0) x axis (1, 0, 0)
  dimension "d108" = 5

design "Base"
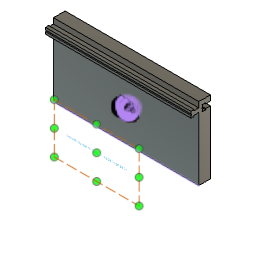
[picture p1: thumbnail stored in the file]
parameter "wall_anchor_height" = 60
parameter "wall_anchor_width" = 20
parameter "wall_anchor_angle" = 45
parameter "width_per_slot" = 40
parameter "slot_inner_width" = 8.5
parameter "slot_inner_height" = 4.5
parameter "slot_outer_width" = 5.6
parameter "slot_outer_height" = 6.5
parameter "slot_dept" = 15
parameter "print_tolerance" = 0.12
parameter "base_plate_thickness" = 16
parameter "base_plate_slot_height" = 50
parameter "wall_anchor_angle_rounded_border" = 1.5
parameter "base_plate_screw_hole_diameter" = 4
parameter "base_plate_screw_head_diameter" = 8
parameter "base_plate_screw_head_height" = 4
parameter "base_plate_screw_hole_side_distance" = 7
parameter "slot_screw_head_width" = 4.42 (= "4.3 mm + print_tolerance")
parameter "slot_screw_thread_width" = 2.12 (= "2 mm + print_tolerance")
parameter "slot_screw_head_height" = 2.12 (= "2 mm + print_tolerance")
parameter "width" = 200
parameter "filament_hole_width" = 1.7
parameter "plate_height" = 80
sketch "Side" plane through (0, 0, 0) normal (1, 0, 0) x axis (0, 1, 0)
  line L1 (39.6118, 0) -> (19.6118, 0)
  line L2 (39.6118, 60) -> (39.6118, 0)
  line L3 (19.6118, 60) -> (39.6118, 60)
  line L4 (19.6118, 0) -> (19.6118, 60)
  line L5 (39.6118, 39.6118) -> (0, 0)
  line L6 (56.0196, 0) -> (0, 0)
  point P1 (0, 0)
  point P6 (0, 0)
  point P7 (39.6118, 39.6118)
  point P2 (19.6118, 0)
  point P3 (39.6118, 0)
  point P5 (19.6118, 60)
  horizontal L1
  vertical L2
  horizontal L3
  vertical L4
  horizontal L6
  coincident P1 P6
  coincident L2 P7
  dimension "d4" distance P2 P3 = 20 (= "wall_anchor_width")
  dimension "d5" distance P2 P5 = 60 (= "wall_anchor_height")
  dimension "d6" angle L5 L6 = 45 (= "wall_anchor_angle")
extrude "Extrude1" new body sketch "Side" profile of L1 L2 L3 L4 L5 along normal blind 40 (= "width_per_slot")
sketch "Slot LeftToRight" plane through (0, 0, 0) normal (-1, 0, 0) x axis (0, -1, 0)
  line L1 (-19.6118, 60) -> (-19.6118, 19.6118)
  line L2 (-39.6118, 60) -> (-19.6118, 60)
  line L3 (-39.6118, 39.6118) -> (-39.6118, 60)
  line L4 (-19.6118, 19.6118) -> (-39.6118, 39.6118)
  line L5 (-39.6118, 52.6059) -> (-39.6118, 49.8059)
  line L6 (-39.6118, 47.0059) -> (-39.6118, 49.8059)
  line L7 (-33.1118, 52.6059) -> (-39.6118, 52.6059)
  line L8 (-28.6118, 49.8059) -> (-39.6118, 49.8059)
  line L9 (-28.6118, 54.0559) -> (-28.6118, 49.8059)
  line L10 (-33.1118, 54.0559) -> (-28.6118, 54.0559)
  line L11 (-33.1118, 52.6059) -> (-33.1118, 54.0559)
  line L12 (-28.6118, 45.5559) -> (-28.6118, 49.8059)
  line L13 (-33.1118, 45.5559) -> (-28.6118, 45.5559)
  line L14 (-33.1118, 47.0059) -> (-33.1118, 45.5559)
  line L15 (-33.1118, 47.0059) -> (-39.6118, 47.0059)
  point P6 (-39.6118, 49.8059)
  point P7 (-39.6118, 52.6059)
  point P17 (-39.6118, 47.0059)
  point P9 (-33.1118, 52.6059)
  point P16 (-33.1118, 47.0059)
  point P10 (-28.6118, 49.8059)
  point P13 (-28.6118, 49.8059)
  point P11 (-28.6118, 54.0559)
  point P14 (-28.6118, 45.5559)
  point P12 (-33.1118, 54.0559)
  point P15 (-33.1118, 45.5559)
  midpoint L3 P6
  parallel L3 L5
  parallel L3 L6
  perpendicular L3 L7
  perpendicular L6 L8
  perpendicular L8 L9
  perpendicular L9 L10
  symmetric P7 L8 P17
  symmetric P9 L8 P16
  symmetric P10 L8 P13
  symmetric L8 P11 P14
  symmetric L8 P12 P15
  dimension "d80" distance P6 P7 = 2.8 (= "slot_outer_width / 2")
  dimension "d82" distance P7 P9 = 6.5 (= "slot_outer_height")
  dimension "d84" distance P6 P10 = 11 (= "slot_outer_height + slot_inner_height")
  dimension "d85" distance P10 P11 = 4.25 (= "slot_inner_width / 2")
  dimension "d86" distance P11 P12 = 4.5 (= "slot_inner_height")
extrude "Extrude3" cut sketch "Slot LeftToRight" profile of L3 L5 L6 L7 L9 L10 L11 L12 L13 L14 L15 against normal blind 40 (magnitude of "width_per_slot * -1")
sketch "Plate" plane through (0, 39.6118, 0) normal (0, 1, 0) x axis (-1, 0, 0)
  line L1 (0, 39.6118) -> (-40, 39.6118)
  line L2 (-40, 60) -> (0, 60)
  line L3 (0, 10) -> (0, 60)
  line L4 (-40, 10) -> (-40, 60)
  line L5 (-40, 10) -> (0, 10)
  line L6 (-40, 47.0059) -> (0, 47.0059)
  line L7 (-40, 52.6059) -> (-40, 60)
  line L8 (0, 60) -> (0, 52.6059)
  line L9 (0, 52.6059) -> (-40, 52.6059)
  line L10 (-40, 60) -> (0, 60)
  line L11 (-40, 39.6118) -> (-40, 47.0059)
  line L12 (0, 47.0059) -> (0, 39.6118)
  point P2 (0, 60)
  point P3 (-40, 60)
  point P4 (0, 10)
  point P5 (-40, 10)
  perpendicular L1 L3
  perpendicular L1 L4
  dimension "d36" distance P2 P3 = 40 (= "width_per_slot")
  dimension "d37" distance P2 P4 = 50 (= "base_plate_slot_height")
  dimension "d39" distance P3 P5 = 50 (= "base_plate_slot_height")
extrude "Extrude6" new body sketch "Plate" profile of L1 L2 L3 L4 L5 L6 L7 L8 L9 L10 along normal blind 16 (= "base_plate_thickness") bodies "Base plate with slot"
sketch "Slot" plane through (0, 0, 0) normal (-1, 0, 0) x axis (0, -1, 0)
  line L1 (-19.6118, 60) -> (-19.6118, 19.6118)
  line L2 (-39.6118, 60) -> (-19.6118, 60)
  line L3 (-39.6118, 52.6059) -> (-39.6118, 60)
  line L4 (-33.1118, 52.6059) -> (-39.6118, 52.6059)
  line L5 (-33.1118, 54.0559) -> (-33.1118, 52.6059)
  line L6 (-28.6118, 54.0559) -> (-33.1118, 54.0559)
  line L7 (-28.6118, 45.5559) -> (-28.6118, 54.0559)
  line L8 (-33.1118, 45.5559) -> (-28.6118, 45.5559)
  line L9 (-33.1118, 47.0059) -> (-33.1118, 45.5559)
  line L10 (-39.6118, 47.0059) -> (-33.1118, 47.0059)
  line L11 (-39.6118, 39.6118) -> (-39.6118, 47.0059)
  line L12 (-19.6118, 19.6118) -> (-39.6118, 39.6118)
  line L13 (-33.1118, 52.6059) -> (-39.6118, 52.6059)
  line L14 (-33.1118, 54.0559) -> (-33.1118, 52.6059)
  line L15 (-28.6118, 54.0559) -> (-33.1118, 54.0559)
  line L16 (-28.6118, 45.5559) -> (-28.6118, 54.0559)
  line L17 (-33.1118, 45.5559) -> (-28.6118, 45.5559)
  line L18 (-33.1118, 47.0059) -> (-33.1118, 45.5559)
  line L19 (-39.6118, 47.0059) -> (-33.1118, 47.0059)
  line L20 (-39.6118, 10) -> (-39.6118, 60)
  line L21 (-32.9918, 52.4859) -> (-39.6118, 52.4859)
  line L22 (-32.9918, 53.9359) -> (-32.9918, 52.4859)
  line L23 (-28.7318, 53.9359) -> (-32.9918, 53.9359)
  line L24 (-28.7318, 45.6759) -> (-28.7318, 53.9359)
  line L25 (-32.9918, 45.6759) -> (-28.7318, 45.6759)
  line L26 (-32.9918, 47.1259) -> (-32.9918, 45.6759)
  line L27 (-39.6118, 47.1259) -> (-32.9918, 47.1259)
  line L28 (-33.1118, 52.6059) -> (-39.6118, 52.6059)
  line L29 (-33.1118, 52.6059) -> (-33.1118, 54.0559)
  line L30 (-28.6118, 54.0559) -> (-33.1118, 54.0559)
  line L31 (-28.6118, 45.5559) -> (-28.6118, 54.0559)
  line L32 (-33.1118, 45.5559) -> (-28.6118, 45.5559)
  line L33 (-33.1118, 47.0059) -> (-33.1118, 45.5559)
  line L34 (-39.6118, 47.0059) -> (-33.1118, 47.0059)
  line L35 (-39.6118, 47.0059) -> (-39.6118, 52.6059)
  line L36 (-49.1118, 52.6059) -> (-55.6118, 52.6059)
  line L37 (-49.1118, 52.6059) -> (-49.1118, 54.0559)
  line L38 (-44.6118, 54.0559) -> (-49.1118, 54.0559)
  line L39 (-44.6118, 45.5559) -> (-44.6118, 54.0559)
  line L40 (-49.1118, 45.5559) -> (-44.6118, 45.5559)
  line L41 (-49.1118, 47.0059) -> (-49.1118, 45.5559)
  line L42 (-55.6118, 47.0059) -> (-49.1118, 47.0059)
  line L43 (-55.6118, 47.0059) -> (-55.6118, 52.6059)
  point P15 (-39.6118, 52.6059)
  point P33 (-39.6118, 52.6059)
  point P16 (-33.1118, 52.6059)
  point P34 (-33.1118, 52.6059)
  point P17 (-33.1118, 54.0559)
  point P35 (-33.1118, 54.0559)
  point P36 (-33.1118, 52.6059)
  point P18 (-28.6118, 54.0559)
  point P37 (-28.6118, 54.0559)
  point P19 (-28.6118, 45.5559)
  point P38 (-28.6118, 45.5559)
  point P10 (-28.6118, 45.5559)
  point P39 (-28.6118, 45.5559)
  point P11 (-33.1118, 45.5559)
  point P40 (-33.1118, 45.5559)
  point P41 (-33.1118, 45.5559)
  point P12 (-33.1118, 47.0059)
  point P42 (-33.1118, 47.0059)
  point P21 (-33.1118, 47.0059)
  point P43 (-33.1118, 47.0059)
  point P22 (-39.6118, 47.0059)
  point P44 (-39.6118, 47.0059)
  point P45 (-39.6118, 52.6059)
  point P46 (-39.6118, 47.0059)
  coincident P15 P33
  coincident P16 P34
  coincident P17 P35
  coincident P16 P36
  coincident P18 P37
  coincident P19 P38
  coincident P10 P39
  coincident P11 P40
  coincident P11 P41
  coincident P12 P42
  coincident P21 P43
  coincident P22 P44
  coincident P15 P45
  coincident P22 P46
  dimension "d91" = 0.12 (= "print_tolerance")
  dimension "d96" R-Pattern1-uDistance = -16 (= "base_plate_thickness * -1")
  dimension "d97" R-Pattern1-vDistance = 0
extrude "Extrude7" add sketch "Slot" profile of L20 L24 L23 L27 L22 L25 L26 L21 against normal blind 40 (magnitude of "width_per_slot * -1")
extrude "Extrude8" cut sketch "Slot" profile of L36 L37 L38 L39 L40 L41 L42 L43 no distance stored
sketch "Sketch3" plane through (0, 0, 0) normal (-1, 0, 0) x axis (0, -1, 0)
  line L1 (-32.9918, 47.1259) -> (-39.6118, 47.1259)
  line L2 (-32.9918, 45.6759) -> (-32.9918, 47.1259)
  line L3 (-28.7318, 45.6759) -> (-32.9918, 45.6759)
  line L4 (-28.7318, 53.9359) -> (-28.7318, 45.6759)
  line L5 (-32.9918, 53.9359) -> (-28.7318, 53.9359)
  line L6 (-32.9918, 52.4859) -> (-32.9918, 53.9359)
  line L7 (-39.6118, 52.4859) -> (-32.9918, 52.4859)
  line L8 (-44.6118, 45.5559) -> (-44.6118, 54.0559)
  line L9 (-32.9918, 52.4859) -> (-39.6118, 52.4859)
  line L10 (-32.9918, 53.9359) -> (-32.9918, 52.4859)
  line L11 (-28.7318, 53.9359) -> (-32.9918, 53.9359)
  line L12 (-28.7318, 45.6759) -> (-28.7318, 53.9359)
  line L13 (-32.9918, 45.6759) -> (-28.7318, 45.6759)
  line L14 (-32.9918, 47.1259) -> (-32.9918, 45.6759)
  line L15 (-39.6118, 47.1259) -> (-32.9918, 47.1259)
  line L16 (-39.6118, 47.1259) -> (-39.6118, 52.4859)
  line L17 (-55.6118, 52.4859) -> (-48.9918, 52.4859)
  line L18 (-48.9918, 52.4859) -> (-48.9918, 53.9359)
  line L19 (-48.9918, 53.9359) -> (-44.7318, 53.9359)
  line L20 (-44.7318, 45.6759) -> (-44.7318, 53.9359)
  line L21 (-48.9918, 45.6759) -> (-44.7318, 45.6759)
  line L22 (-48.9918, 47.1259) -> (-48.9918, 45.6759)
  line L23 (-55.6118, 47.1259) -> (-48.9918, 47.1259)
  line L24 (-55.6118, 47.1259) -> (-55.6118, 52.4859)
  line L25 (-55.6118, 47.0059) -> (-49.1118, 47.0059)
  line L26 (-55.6118, 10) -> (-55.6118, 47.0059)
  line L27 (-39.6118, 10) -> (-55.6118, 10)
  line L28 (-39.6118, 47.1259) -> (-39.6118, 10)
  line L29 (-39.6118, 60) -> (-39.6118, 52.4859)
  line L30 (-55.6118, 60) -> (-39.6118, 60)
  line L31 (-55.6118, 52.6059) -> (-55.6118, 60)
  line L32 (-49.1118, 52.6059) -> (-55.6118, 52.6059)
  line L33 (-49.1118, 54.0559) -> (-49.1118, 52.6059)
  line L34 (-44.6118, 54.0559) -> (-49.1118, 54.0559)
  line L35 (-49.1118, 45.5559) -> (-44.6118, 45.5559)
  line L36 (-49.1118, 47.0059) -> (-49.1118, 45.5559)
  point P9 (-39.6118, 52.4859)
  point P20 (-39.6118, 52.4859)
  point P19 (-39.6118, 47.1259)
  point P21 (-39.6118, 47.1259)
  coincident P9 P20
  coincident P19 P21
  dimension "d105" R-Pattern1-vDistance = 0
extrude "Extrude3" new body sketch "Sketch3" profile of L17 L18 L19 L20 L21 L22 L23 L24 against normal blind 40 (magnitude of "width_per_slot * -1")
sketch "Screw hole" plane through (0, 28.6118, 0) normal (0, 1, 0) x axis (-1, 0, 0)
  line L1 (0, 54.0559) -> (0, 45.5559)
  line L2 (-40, 54.0559) -> (0, 54.0559)
  line L3 (-40, 45.5559) -> (-40, 54.0559)
  line L4 (0, 45.5559) -> (-40, 45.5559)
  line L5 (0, 45.5559) -> (-40, 54.0559)
  line L6 (-40, 45.5559) -> (0, 54.0559)
  circle C1 centre (-20, 49.8059) radius 2.21
  circle C2 centre (-20, 49.8059) radius 1.06
  point P4 (-40, 54.0559)
  point P6 (-40, 54.0559)
  point P2 (0, 45.5559)
  point P7 (0, 45.5559)
  point P3 (0, 54.0559)
  point P8 (0, 54.0559)
  point P5 (-40, 45.5559)
  point P9 (-40, 45.5559)
  point P10 (-20, 49.8059)
  coincident P4 P6
  coincident P2 P7
  coincident P3 P8
  coincident P5 P9
  midpoint L5 P10
  concentric C1 C2
  dimension "d119" diameter C1 = 4.42 (= "slot_screw_head_width")
  dimension "d120" diameter C2 = 2.12 (= "slot_screw_thread_width")
extrude "Extrude4" cut sketch "Screw hole" profile of C2 against normal blind 2000
extrude "Extrude5" cut sketch "Screw hole" profile of C1 C2 no distance stored
fillet "Fillet1" radius 1.5 (= "wall_anchor_angle_rounded_border")
work_plane "WorkPlane1" sketch "Slot LeftToRight" AlongDistance -20 (= "-width_per_slot / 2")
sketch "Screw head" plane through (20, 0, 0) normal (-1, 0, 0) x axis (0, -1, 0)
  line L1 (-28.6118, 52.0159) -> (-28.6118, 47.5959)
  line L2 (-26.4918, 52.0159) -> (-26.4918, 47.5959)
  line L3 (-26.4918, 48.7459) -> (-26.4918, 50.8659)
  line L4 (-26.4918, 50.8659) -> (-28.6118, 52.0159)
  line L5 (-26.4918, 52.0159) -> (-28.6118, 52.0159)
  point P3 (-28.6118, 52.0159)
  point P8 (-28.6118, 52.0159)
  point P6 (-26.4918, 50.8659)
  point P9 (-26.4918, 50.8659)
  point P10 (-28.6118, 52.0159)
  point P5 (-26.4918, 52.0159)
  point P11 (-26.4918, 52.0159)
  coincident P3 P8
  coincident P6 P9
  coincident P3 P10
  coincident P5 P11
revolve "Revolve1" sketch "Screw head" AlongAngle 360
sketch "Plate" plane through (0, 39.6118, 0) normal (0, 1, 0) x axis (-1, 0, 0)
  line L1 (0, 39.6118) -> (-40, 39.6118)
  line L2 (-40, 60) -> (0, 60)
  line L3 (0, 10) -> (0, 60)
  line L4 (-40, 10) -> (-40, 60)
  line L5 (-40, 10) -> (0, 10)
  line L6 (-40, 47.0059) -> (0, 47.0059)
  line L7 (-40, 39.6118) -> (-40, 47.0059)
  line L8 (0, 47.0059) -> (0, 39.6118)
  line L9 (0, 52.6059) -> (-40, 52.6059)
  line L10 (-40, 60) -> (0, 60)
  line L11 (0, 60) -> (0, 52.6059)
  line L12 (-40, 52.6059) -> (-40, 60)
  point P2 (0, 60)
  point P3 (-40, 60)
  point P4 (0, 10)
  point P5 (-40, 10)
  perpendicular L1 L3
  perpendicular L1 L4
  dimension "d36_1" distance P2 P3 = 40 (= "width_per_slot")
  dimension "d37_1" distance P2 P4 = 50 (= "base_plate_slot_height")
  dimension "d39_1" distance P3 P5 = 50 (= "base_plate_slot_height")
extrude "Extrude6" new body sketch "Plate" profile of L1 L2 L3 L4 L5 L6 L7 L8 L9 L10 along normal blind 16 (= "base_plate_thickness") named "d89_1" bodies "Base plate with slot"
sketch "Slot" plane through (0, 0, 0) normal (-1, 0, 0) x axis (0, -1, 0)
  line L1 (-19.6118, 60) -> (-19.6118, 23.2332)
  line L2 (-39.6118, 60) -> (-19.6118, 60)
  line L3 (-39.6118, 52.6059) -> (-39.6118, 60)
  line L4 (-33.1118, 52.6059) -> (-39.6118, 52.6059)
  line L5 (-33.1118, 54.0559) -> (-33.1118, 52.6059)
  line L6 (-28.6118, 54.0559) -> (-33.1118, 54.0559)
  line L7 (-28.6118, 45.5559) -> (-28.6118, 54.0559)
  line L8 (-33.1118, 45.5559) -> (-28.6118, 45.5559)
  line L9 (-33.1118, 47.0059) -> (-33.1118, 45.5559)
  line L10 (-39.6118, 47.0059) -> (-33.1118, 47.0059)
  line L11 (-39.6118, 39.6118) -> (-39.6118, 47.0059)
  line L12 (-22.1725, 22.1725) -> (-39.6118, 39.6118)
  line L13 (-33.1118, 52.6059) -> (-39.6118, 52.6059)
  line L14 (-33.1118, 54.0559) -> (-33.1118, 52.6059)
  line L15 (-28.6118, 54.0559) -> (-33.1118, 54.0559)
  line L16 (-28.6118, 45.5559) -> (-28.6118, 54.0559)
  line L17 (-33.1118, 45.5559) -> (-28.6118, 45.5559)
  line L18 (-33.1118, 47.0059) -> (-33.1118, 45.5559)
  line L19 (-39.6118, 47.0059) -> (-33.1118, 47.0059)
  line L20 (-39.6118, 10) -> (-39.6118, 60)
  line L21 (-32.9918, 52.4859) -> (-39.6118, 52.4859)
  line L22 (-32.9918, 53.9359) -> (-32.9918, 52.4859)
  line L23 (-28.7318, 53.9359) -> (-32.9918, 53.9359)
  line L24 (-28.7318, 45.6759) -> (-28.7318, 53.9359)
  line L25 (-32.9918, 45.6759) -> (-28.7318, 45.6759)
  line L26 (-32.9918, 47.1259) -> (-32.9918, 45.6759)
  line L27 (-39.6118, 47.1259) -> (-32.9918, 47.1259)
  line L28 (-33.1118, 52.6059) -> (-39.6118, 52.6059)
  line L29 (-33.1118, 52.6059) -> (-33.1118, 54.0559)
  line L30 (-28.6118, 54.0559) -> (-33.1118, 54.0559)
  line L31 (-28.6118, 45.5559) -> (-28.6118, 54.0559)
  line L32 (-33.1118, 45.5559) -> (-28.6118, 45.5559)
  line L33 (-33.1118, 47.0059) -> (-33.1118, 45.5559)
  line L34 (-39.6118, 47.0059) -> (-33.1118, 47.0059)
  line L35 (-39.6118, 47.0059) -> (-39.6118, 52.6059)
  line L36 (-49.1118, 52.6059) -> (-55.6118, 52.6059)
  line L37 (-49.1118, 52.6059) -> (-49.1118, 54.0559)
  line L38 (-44.6118, 54.0559) -> (-49.1118, 54.0559)
  line L39 (-44.6118, 45.5559) -> (-44.6118, 54.0559)
  line L40 (-49.1118, 45.5559) -> (-44.6118, 45.5559)
  line L41 (-49.1118, 47.0059) -> (-49.1118, 45.5559)
  line L42 (-55.6118, 47.0059) -> (-49.1118, 47.0059)
  line L43 (-55.6118, 47.0059) -> (-55.6118, 52.6059)
  arc A1 centre (-21.1118, 23.2332) radius 1.5 clockwise from (-19.6118, 23.2332) to (-22.1725, 22.1725)
  point P15 (-39.6118, 52.6059)
  point P33 (-39.6118, 52.6059)
  point P16 (-33.1118, 52.6059)
  point P34 (-33.1118, 52.6059)
  point P17 (-33.1118, 54.0559)
  point P35 (-33.1118, 54.0559)
  point P36 (-33.1118, 52.6059)
  point P18 (-28.6118, 54.0559)
  point P37 (-28.6118, 54.0559)
  point P19 (-28.6118, 45.5559)
  point P38 (-28.6118, 45.5559)
  point P10 (-28.6118, 45.5559)
  point P39 (-28.6118, 45.5559)
  point P11 (-33.1118, 45.5559)
  point P40 (-33.1118, 45.5559)
  point P41 (-33.1118, 45.5559)
  point P12 (-33.1118, 47.0059)
  point P42 (-33.1118, 47.0059)
  point P21 (-33.1118, 47.0059)
  point P43 (-33.1118, 47.0059)
  point P22 (-39.6118, 47.0059)
  point P44 (-39.6118, 47.0059)
  point P45 (-39.6118, 52.6059)
  point P46 (-39.6118, 47.0059)
  coincident P15 P33
  coincident P16 P34
  coincident P17 P35
  coincident P16 P36
  coincident P18 P37
  coincident P19 P38
  coincident P10 P39
  coincident P11 P40
  coincident P11 P41
  coincident P12 P42
  coincident P21 P43
  coincident P22 P44
  coincident P15 P45
  coincident P22 P46
  dimension "d91_1" = 0.12 (= "print_tolerance")
  dimension "d96_1" R-Pattern1-uDistance = -16 (= "base_plate_thickness * -1")
  dimension "d97_1" R-Pattern1-vDistance = 0
extrude "Extrude8" cut sketch "Slot" profile of L36 L37 L38 L39 L40 L41 L42 L43 no distance stored
sketch "Screw" plane through (0, 55.6118, 0) normal (0, 1, 0) x axis (-1, 0, 0)
  line L1 (-40, 47.0059) -> (0, 47.0059)
  line L2 (-40, 10) -> (-40, 47.0059)
  line L3 (0, 10) -> (-40, 10)
  line L4 (0, 47.0059) -> (0, 10)
  line L5 (-33, 17) -> (-33, 40.0059)
  line L6 (-7, 17) -> (-33, 17)
  line L7 (-7, 40.0059) -> (-7, 17)
  line L8 (-33, 40.0059) -> (-7, 40.0059)
  circle C1 centre (-33, 17) radius 4
  circle C2 centre (-33, 17) radius 2
  point P7 (-33, 17)
  point P10 (-33, 17)
  coincident P7 P10
  concentric C1 C2
  dimension "d127" = -7 (= "base_plate_screw_hole_side_distance * -1")
  dimension "d128" diameter C1 = 8
  dimension "d129" diameter C2 = 4
rectangular_pattern "R-Pattern2" countU 5 (= "floor(( width / mm ) / ( width_per_slot / cm * 10 ))") uSpaceDistance 40 (= "width_per_slot") vSpaceDistance 0 bodies "Wall anchor part (1)", "Wall anchor part (2)", "Wall anchor part (3)", "Wall anchor part (4)"
work_plane "WorkPlane2"
extrude "Extrude12" new body of existing geometry no distance stored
